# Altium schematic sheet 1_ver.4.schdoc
size 302 x 215 mm; Name: A_A4; Symbol: A_A4; Device: A_A4; @Project Name: VisionGuard; REV: 4; Date: 2025-06-20; Sheet: 1/1; Draw By: Mohammed Saleh; Company: NXU; Convert to PCB: yes; Add into BOM: yes; spicePre: .; @Page No: 1; @Page Count: 1; @Schematic Name: eye-protect_2; @Board Name: eye-protect_2; @Update Date: 2025-07-19; @Create Time: 02:39:35; @Update Time: 13:09:37; @Page Name: ver.4; @Create Date: 2025-07-10
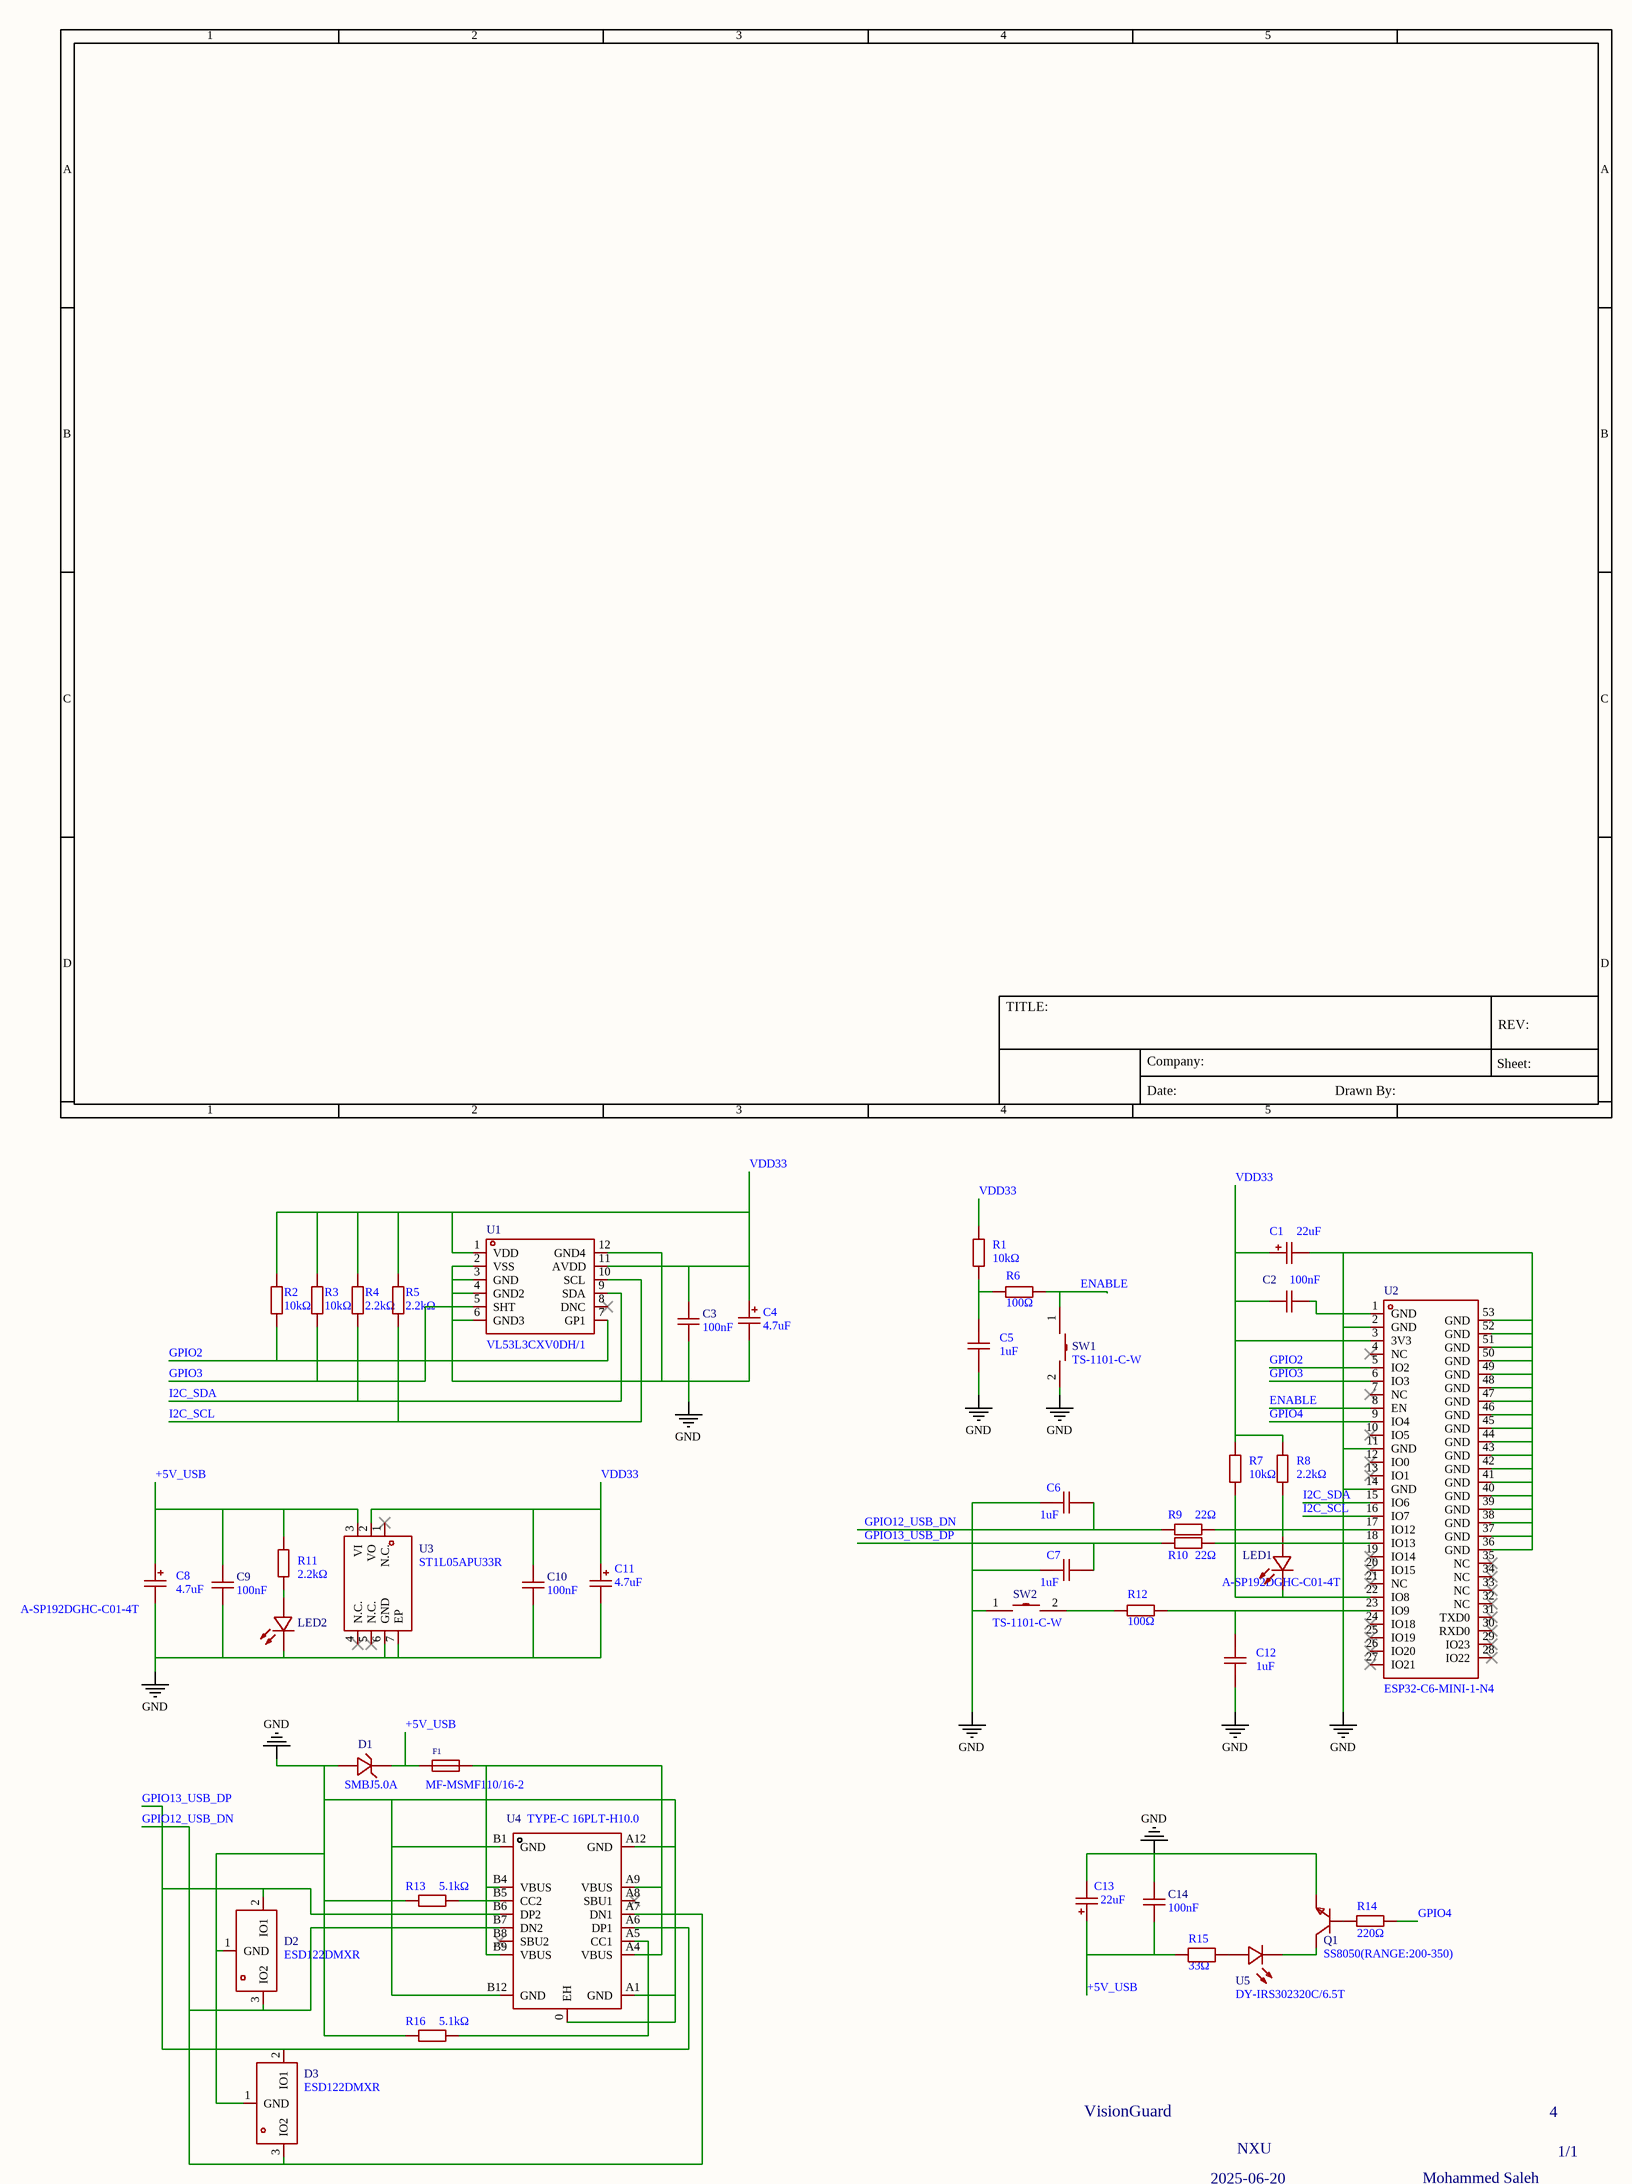
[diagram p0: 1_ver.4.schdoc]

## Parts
C1  22uF  [CASE-A_3216]
C2  100nF  [C0402]
C3  100nF  [C0402]
C4  4.7uF  [CAP-SMD_L2.0-W1.3-FD]
C5  1uF  [C0603]
C6  1uF  [C0603]
C7  1uF  [C0603]
C8  4.7uF  [CAP-SMD_L2.0-W1.3-FD]
C9  100nF  [C0402]
C10  100nF  [C0402]
C11  4.7uF  [CAP-SMD_L2.0-W1.3-FD]
C12  1uF  [C0603]
C13  22uF  [CASE-A_3216]
C14  100nF  [C0402]
D1  SMBJ5.0A  [SMB_L4.6-W3.6-LS5.3-RD]
D2  ESD122DMXR  [X2SON-3_L1.0-W0.6-L]
D3  ESD122DMXR  [X2SON-3_L1.0-W0.6-L]
F1  MF-MSMF110/16-2  [F1812]
LED1  A-SP192DGHC-C01-4T  [LED0603-FD]
LED2  A-SP192DGHC-C01-4T  [LED0603-FD]
Q1  SS8050(RANGE:200-350)  [SOT-23-3_L2.9-W1.3-P1.90-LS2.4-BR]
R1  10kΩ  [R0603]
R2  10kΩ  [R0603]
R3  10kΩ  [R0603]
R4  2.2kΩ  [R0603]
R5  2.2kΩ  [R0603]
R6  100Ω  [R0603]
R7  10kΩ  [R0603]
R8  2.2kΩ  [R0603]
R9  22Ω  [R0603]
R10  22Ω  [R0603]
R11  2.2kΩ  [R0603]
R12  100Ω  [R0603]
R13  5.1kΩ  [R0603]
R14  220Ω  [R0603]
R15  33Ω  [R1206]
R16  5.1kΩ  [R0603]
SW1  TS-1101-C-W  [SW-SMD_L6.0-W3.3-LS8.0]
SW2  TS-1101-C-W  [SW-SMD_L6.0-W3.3-LS8.0]
U1  VL53L3CXV0DH/1  [OPTO-SMD_12P_VL53L3CXV0DH]
U2  ESP32-C6-MINI-1-N4  [WIFIM-SMD_61P-L16.6-W13.2-P0.80-ESP32-C6-MINI-1-N4]
U3  ST1L05APU33R  [DFN-6_L3.0-W3.0-P0.95-BL-EP-1]
U4  TYPE-C 16PLT-H10.0  [TYPE-C-SMD_USB4120-03-C]
U5  DY-IRS302320C/6.5T  [LED-SMD_L3.0-W2.0-R-RD]

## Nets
GND: C1.2 C2.1 C3.2 C4.2 C5.2 C6.2 C7.2 C8.2 C9.2 C10.2 C11.2 C12.2 C13.2 C14.1 D1.2 D2.1(GND) D3.1(GND) LED2.1(K) Q1.2(E) R9.2 R13.1 R16.1 SW1.2 SW2.1 U1.2(VSS) U1.3(GND) U1.4(GND2) U1.6(GND3) U1.12(GND4) U2.1(GND) U2.2(GND) U2.11(GND) U2.14(GND) U2.17(IO12) U2.36(GND) U2.37(GND) U2.38(GND) U2.39(GND) U2.40(GND) U2.41(GND) U2.42(GND) U2.43(GND) U2.44(GND) U2.45(GND) U2.46(GND) U2.47(GND) U2.48(GND) U2.49(GND) U2.50(GND) U2.51(GND) U2.52(GND) U2.53(GND) U3.6(GND) U3.7(EP) U4.0(EH) U4.A1(GND) U4.A12(GND) U4.B1(GND) U4.B12(GND)
+5V_USB: C8.1 C9.1 C13.1 C14.2 D1.1 F1.1 R11.1 R15.1 U3.3(VI)
ENABLE: R6.2 SW1.1 U2.8(EN)
GPIO2: R2.1 U1.7(GP1) U2.5(IO2)
GPIO3: R3.1 U1.5(SHT) U2.6(IO3)
GPIO4: R14.1 U2.9(IO4)
GPIO12_USB_DN: C6.1 D2.3(IO2) D3.3(IO2) R9.1 U4.A7(DN1) U4.B7(DN2)
GPIO13_USB_DP: C7.1 D2.2(IO1) D3.2(IO1) R10.1 U4.A6(DP1) U4.B6(DP2)
I2C_SCL: R5.1 U1.10(SCL) U2.16(IO7)
I2C_SDA: R4.1 U1.9(SDA) U2.15(IO6)
VDD33: C1.1 C2.2 C3.1 C4.1 C10.1 C11.1 R1.2 R2.2 R3.2 R4.2 R5.2 R7.2 R8.2 U1.1(VDD) U1.11(AVDD) U2.3(3V3) U3.2(VO)
NetC5_1: C5.1 R1.1 R6.1
NetC12_1: C12.1 R12.2 U2.23(IO9)
NetF1_2: F1.2 U4.A4(VBUS) U4.A9(VBUS) U4.B4(VBUS) U4.B9(VBUS)
NetLED1_1: LED1.1(K) R7.1 U2.22(IO8)
NetLED1_2: LED1.2(A) R8.1
NetLED2_2: LED2.2(A) R11.2
NetQ1_1: Q1.1(B) R14.2
NetQ1_3: Q1.3(C) U5.2(-)
NetR10_2: R10.2 U2.18(IO13)
NetR12_1: R12.1 SW2.2
NetR13_2: R13.2 U4.B5(CC2)
NetR15_2: R15.2 U5.1(+)
NetR16_2: R16.2 U4.A5(CC1)

Not connected (* = marked no-connect by the designer): U1 8(DNC)*; U2 4(NC)* 7(NC)* 10(IO5)* 12(IO0)* 13(IO1)* 19(IO14)* 20(IO15)* 21(NC)* 24(IO18)* 25(IO19)* 26(IO20)* 27(IO21)* 28(IO22)* 29(IO23)* 30(RXD0)* 31(TXD0)* 32(NC)* 33(NC)* 34(NC)* 35(NC)*; U3 1(N.C.)* 4(N.C.)* 5(N.C.)*; U4 A8(SBU1)* B8(SBU2)*

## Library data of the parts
C1 C13 = TAJA226K010RNJ: Manufacturer: Kyocera AVX; Add into BOM: yes; Tolerance: ±10%; Voltage Rating: 10V; Equivalent Series Resistance(ESR): 3Ω@100kHz
C2 C3 C9 C10 C14 = CL05B104KA5NNNC: Manufacturer: SAMSUNG(三星); Add into BOM: yes; Tolerance: ±10%
C4 C8 C11 = TAJR475K010RNJ: Manufacturer: Kyocera AVX; Add into BOM: yes; Tolerance: ±10%; Equivalent Series Resistance(ESR): 9Ω@100kHz
C5-C7 C12 = CL10A105KB8NNNC: Manufacturer: SAMSUNG(三星); Symbol: CAP; Add into BOM: yes; Tolerance: ±10%; Check: true
D1 = SMBJ5.0A_C83333: Manufacturer: Littelfuse(美国力特); Add into BOM: yes; Reverse Stand-Off Voltage (Vrwm): 5V; Maximum Clamping Voltage: 9.2V; Peak Pulse Current (Ipp)@10/1000us: 65.3A; Peak Pulse Power Dissipation (Ppp)@10/1000us: 600W; Breakdown Voltage: 6.4V; Type: TVS; Check: true
D2 D3 = ESD122DMXR: Manufacturer: TI(德州仪器); Add into BOM: yes; Reverse Stand-Off Voltage (Vrwm): 3.6V; Maximum Clamping Voltage: 8.4V; Peak Pulse Power Dissipation (Ppp): 20W; Breakdown Voltage: 5.1V; Type: ESD; Check: true
F1 = MF-MSMF110/16-2: Manufacturer: BOURNS; Add into BOM: yes; Voltage - Max: 16V; Current - Max: 100A; Hold Current: 1.1A; Trip Current: 2.2A; Resistance - Initial (Ri) (Min): 40mΩ; Resistance - Post Trip (R1) (Max): 210mΩ; Time to Trip(Max): 300ms
LED1 LED2 = A-SP192DGHC-C01-4T: Manufacturer: Amicc(欧密格光电); Symbol: KT-0603R; Add into BOM: yes; Emitted Color: Green; Forward Voltage (VF): 2.4V~3V; Power Dissipation: 70mW; Dominant Wavelength: 520nm~535nm; Lens Color: Colorless Transparent Lens; Luminous Intensity: 225mcd~450mcd; Viewing Angle: 120°; Mounting Sytle: Positive Stick; Check: true
Q1 = SS8050(RANGE:200-350)_C2150: Manufacturer: CJ(江苏长电/长晶); Symbol: SS8050_C2150; Add into BOM: yes; DC Current Gain (hFE@Ic,Vce): 200@800mA,1V; Transition Frequency (fT): 100MHz; Collector Cut-Off Current (Icbo): 100nA; Collector-Emitter Saturation Voltage (VCE(sat)@Ic,Ib): 500mV@800mA,80mA; Check: true
R1-R3 R7 = 0603WAF1002T5E: Manufacturer: UNI-ROYAL(厚声); Symbol: Res; Add into BOM: yes; Tolerance: ±1%; Power(Watts): 100mW; Voltage-Supply(Max): 75V; Temperature Coefficient: ±100ppm/℃; Check: true
R4 R5 R8 R11 = 0603WAF2201T5E_C4190: Manufacturer: UNI-ROYAL(厚声); Symbol: Res; Add into BOM: yes; Tolerance: ±1%; Temperature Coefficient: ±100ppm/℃; Check: true
R6 R12 = 0603WAF1000T5E: Manufacturer: UNI-ROYAL(厚声); Symbol: Res; Add into BOM: yes; Tolerance: ±1%; Temperature Coefficient: ±200ppm/℃; Check: true
R9 R10 = 0603WAF220JT5E: Manufacturer: UNI-ROYAL(厚声); Symbol: Res; Add into BOM: yes; Tolerance: ±1%; Temperature Coefficient: ±100ppm/℃; Check: true
R13 R16 = 0603WAF5101T5E: Manufacturer: UNI-ROYAL(厚声); Symbol: Res; Add into BOM: yes; Tolerance: ±1%; Temperature Coefficient: ±100ppm/℃; Check: true
R14 = 0603WAF2200T5E: Manufacturer: UNI-ROYAL(厚声); Symbol: Res; Add into BOM: yes; Tolerance: ±1%; Temperature Coefficient: ±100ppm/℃; Check: true
R15 = AS0606J0330T5E_C966057: Manufacturer: UNI-ROYAL(厚声); Symbol: AS06W2J0330T5E; Add into BOM: yes; Tolerance: ±5%; Temperature Coefficient: ±100ppm/℃
SW1 SW2 = TS-1101-C-W: Manufacturer: XKB Connectivity(中国星坤); Add into BOM: yes; Circuit: SPST; Actuator Style: Rectangle button; Operating Force: 260gf; Switch Length: 6mm; Switch Width: 3.6mm; Switch Height: 2.5mm; Strike Gundam: 不带; Contact Current: 50mA; Voltage Rating (DC): 12V; Actuator/Cap Color: 白色带淡绿; With Lamp: No; Mechanical Life: 5万次; Check: true
U1 = VL53L3CXV0DH/1: Manufacturer: ST(意法半导体); Add into BOM: yes; Supply Voltage: 2.6V~3.5V; Iinearity Range: 10mm~310cm; Check: true
U2 = ESP32-C6-MINI-1-N4: Manufacturer: ESPRESSIF(乐鑫); Add into BOM: yes; Check: true
U3 = ST1L05APU33R: Manufacturer: ST(意法半导体); Add into BOM: yes; Output Type: Fixed; Maximum Input Voltage: 7V; Output Voltage: 3.3V; Output Current: 1.3A; Power Supply Rejection Ratio (PSRR): 65dB@(120Hz); Dropout Voltage: 500mV@(1.3A); standby current: 650uA; Output Polarity: Positive electrode; Number of Outputs: 1
U4 = TYPE-C 16PLT-H10.0: Manufacturer: SHOU HAN(首韩); Add into BOM: yes; Gender: Female; Number of Contacts: 16P; Number of Ports: 1; Current Rating - Power (Max): 5A; Rated Voltage (Max): 20V; Connect-Disconnect Life: 10,000 times; Core Colour: Black
U5 = DY-IRS302320C/6.5T: Manufacturer: TONYU(东裕); Add into BOM: yes; Vf - Forward Voltage: 1.3V~2V; Power Dissipation: 150mW; Wavelength: 940nm; Radiant Intensity: 150mW/sr; Current - DC Forward (If): 100mA; Reverse Voltage: 5V; View Angle: 35°; Check: true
